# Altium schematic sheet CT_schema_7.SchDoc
size 374 x 245 mm
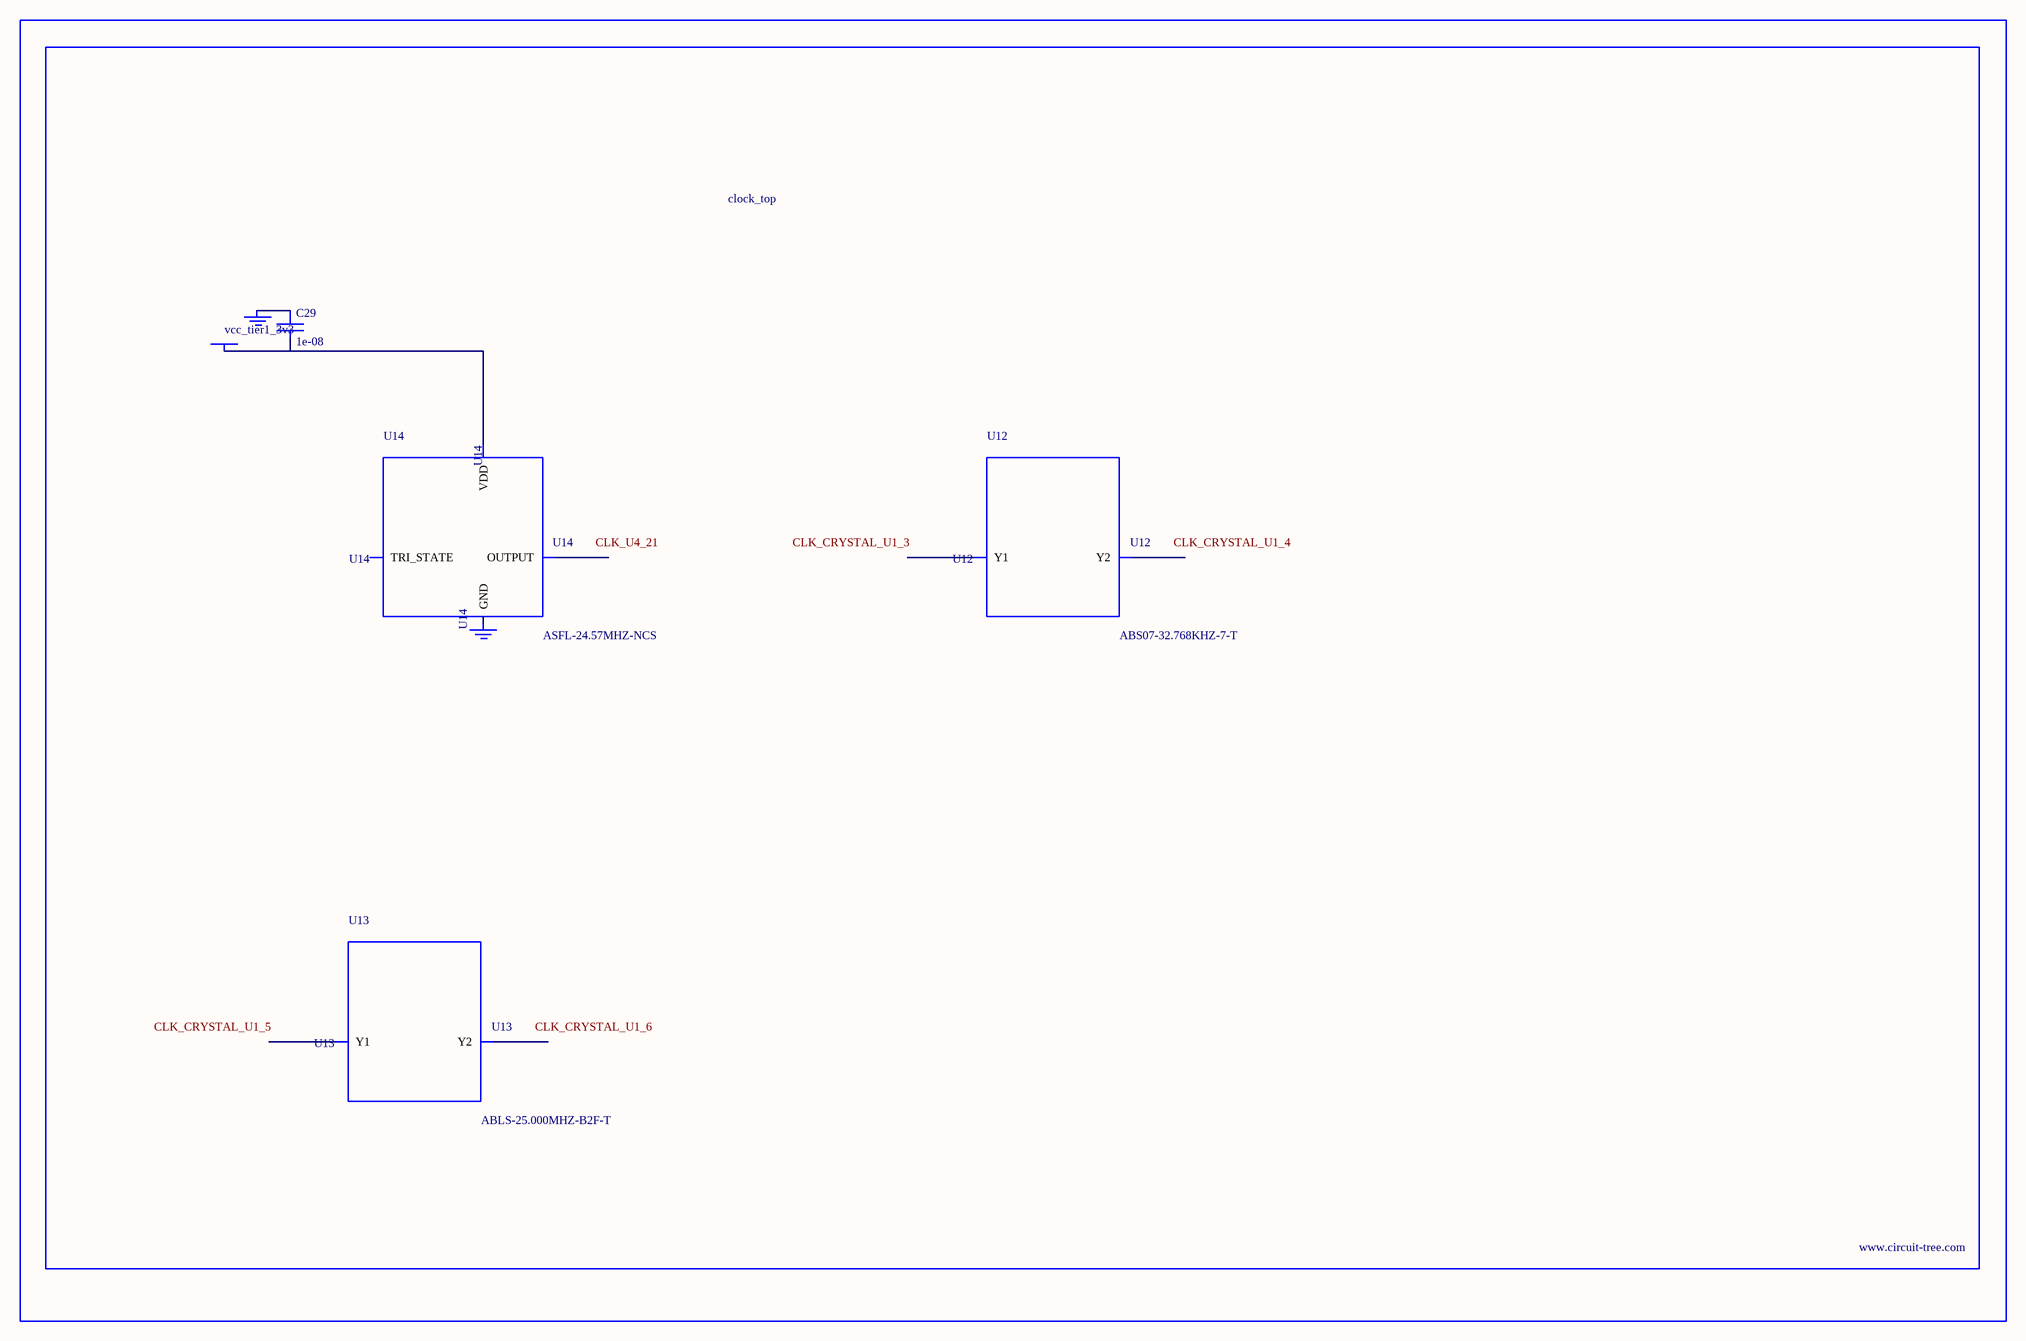
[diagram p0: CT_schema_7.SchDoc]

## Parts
BORDER6  (no value)
C29  1e-08  [C0402]
GND_INSTANCE_6_0  (no value)
GND_INSTANCE_6_1  (no value)
POWER_INSTANCE_6_0  vcc_tier1_3v3
U12  ABS07-32.768KHZ-7-T  [ABS07-32.768KHZ-7-T]
U13  ABLS-25.000MHZ-B2F-T  [ABLS-25.000MHZ-B2F-T]
U14  ASFL-24.57MHZ-NCS  [ASFL1]

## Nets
NetC29_1: C29.1 GND_INSTANCE_6_0.0(GND)
NetC29_2: C29.2 POWER_INSTANCE_6_0.0(PWR) U14.4(VDD)

Not connected (* = marked no-connect by the designer): GND_INSTANCE_6_1 0(GND); U12 1(Y1) 2(Y2); U13 1(Y1) 2(Y2); U14 1(TRI_STATE) 2(GND) 3(OUTPUT)

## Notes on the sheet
- Labels drawn without touching a wire or pin: CLK_CRYSTAL_U1_3, CLK_CRYSTAL_U1_4, CLK_CRYSTAL_U1_5, CLK_CRYSTAL_U1_6, CLK_U4_21

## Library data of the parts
BORDER6 = BORDER_PAGE6
C29 = C0402C103K3RAC
GND_INSTANCE_6_0 GND_INSTANCE_6_1 = GND
POWER_INSTANCE_6_0 = PWR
